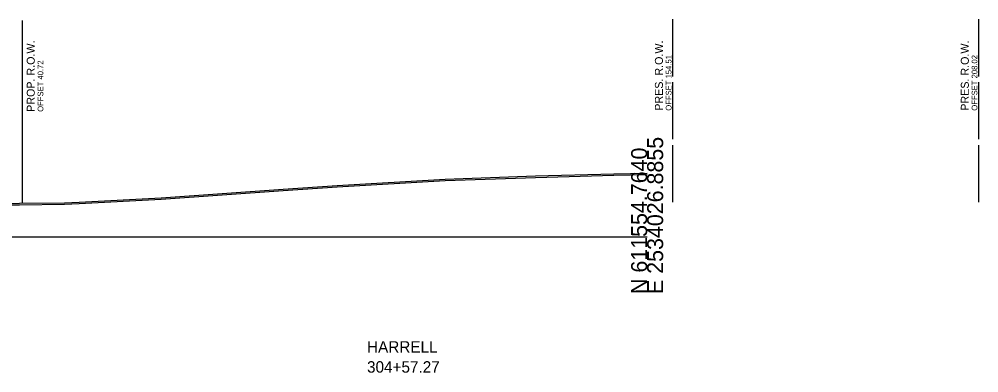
# Model space of a CAD drawing. Extents: x -192 to 2669, y -25 to 8040.
# Drawn here: x 190.2 to 358, y 6476.2 to 6538.1 of the extents above; entities that cross this region are included whole.
import ezdxf

# ---------------------------------------------------------------- set-up
doc = ezdxf.new("R2010")
doc.units = 0
for name, color, linetype in [('DESIGN - ROW - Right-of-Way and Easement Labels', 7, 'Continuous'), ('DESIGN - ROW - Right-of-Way Linework', 7, 'Continuous'), ('DESIGN - SHEET - Light Grid', 7, 'Continuous'), ('DESIGN - TYPICAL - Warning Text', 7, 'Continuous'), ('SURVEY - GROUND - Bottom of Topsoil Layer', 7, 'Continuous'), ('SURVEY - GROUND - Top of Ground', 7, 'Continuous'), ('SURVEY - PROPERTY - ROW Lines', 7, 'Continuous'), ('SURVEY - PROPERTY - ROW Lines Text', 7, 'Continuous')]:
    doc.layers.add(name, color=color, linetype=linetype)

msp = doc.modelspace()

# ---------------------------------------------------------------- linework, layer by layer
at = {"layer": 'DESIGN - ROW - Right-of-Way Linework'}
msp.add_line((190.72, 6505.86), (190.72, 6537.86), dxfattribs=at)
at = {"layer": 'DESIGN - SHEET - Light Grid'}
msp.add_line((150, 6500), (300, 6500), dxfattribs=at)
at = {"layer": 'SURVEY - GROUND - Bottom of Topsoil Layer'}
for p, q in [((264.66, 6509.85), (280.48, 6510.39)), ((280.48, 6510.39), (294.17, 6510.77)), ((294.17, 6510.77), (300, 6510.88)), ((236.34, 6508.08), (245.76, 6508.72)), ((245.76, 6508.72), (264.66, 6509.85)), ((215.01, 6506.59), (236.34, 6508.08)), ((178.73, 6505.49), (190.22, 6505.61)), ((190.22, 6505.61), (198.07, 6505.69)), ((198.07, 6505.69), (200.63, 6505.83)), ((200.63, 6505.83), (215.01, 6506.59))]:
    msp.add_line(p, q, dxfattribs=at)
at = {"layer": 'SURVEY - GROUND - Top of Ground'}
msp.add_lwpolyline([(178.73, 6505.74), (190.22, 6505.86), (198.07, 6505.94), (200.63, 6506.08), (215.01, 6506.84), (236.34, 6508.33), (245.76, 6508.97), (264.66, 6510.1), (280.48, 6510.64), (294.17, 6511.02), (300, 6511.13)], dxfattribs=at)
at = {"layer": 'SURVEY - PROPERTY - ROW Lines'}
for p, q in [((304.51, 6528.06), (304.51, 6538.06)), ((358.02, 6528.06), (358.02, 6538.06)), ((304.51, 6517.06), (304.51, 6527.06)), ((358.02, 6517.06), (358.02, 6527.06)), ((304.51, 6506.06), (304.51, 6516.06)), ((358.02, 6506.06), (358.02, 6516.06))]:
    msp.add_line(p, q, dxfattribs=at)

# ---------------------------------------------------------------- texts
at = {"layer": 'DESIGN - ROW - Right-of-Way and Easement Labels'}
for s, height, p in [('PROP. R.O.W.', 1.4, (192.87, 6521.86)), ('OFFSET 40.72', 1, (194.37, 6521.86))]:
    msp.add_text(s, height=height, rotation=90, dxfattribs=at).set_placement(p)
at = {"layer": 'DESIGN - SHEET - Light Grid'}
for s, p in [('E 2534026.8855', (302.8, 6490)), ('N 611554.7640', (300, 6490))]:
    msp.add_text(s, height=2.8, rotation=90, dxfattribs=at).set_placement(p)
at = {"layer": 'DESIGN - TYPICAL - Warning Text'}
for s, p in [('HARRELL', (251, 6479.75)), ('304+57.27', (251, 6476.25))]:
    msp.add_text(s, height=2, dxfattribs=at).set_placement(p)
at = {"layer": 'SURVEY - PROPERTY - ROW Lines Text'}
for s, height, p in [('PRES. R.O.W.', 1.4, (302.76, 6522.06)), ('PRES. R.O.W.', 1.4, (356.27, 6522.06)), ('OFFSET 154.51', 1, (304.26, 6522.06)), ('OFFSET 208.02', 1, (357.77, 6522.06))]:
    msp.add_text(s, height=height, rotation=90, dxfattribs=at).set_placement(p)

doc.saveas('drawing.dxf')
